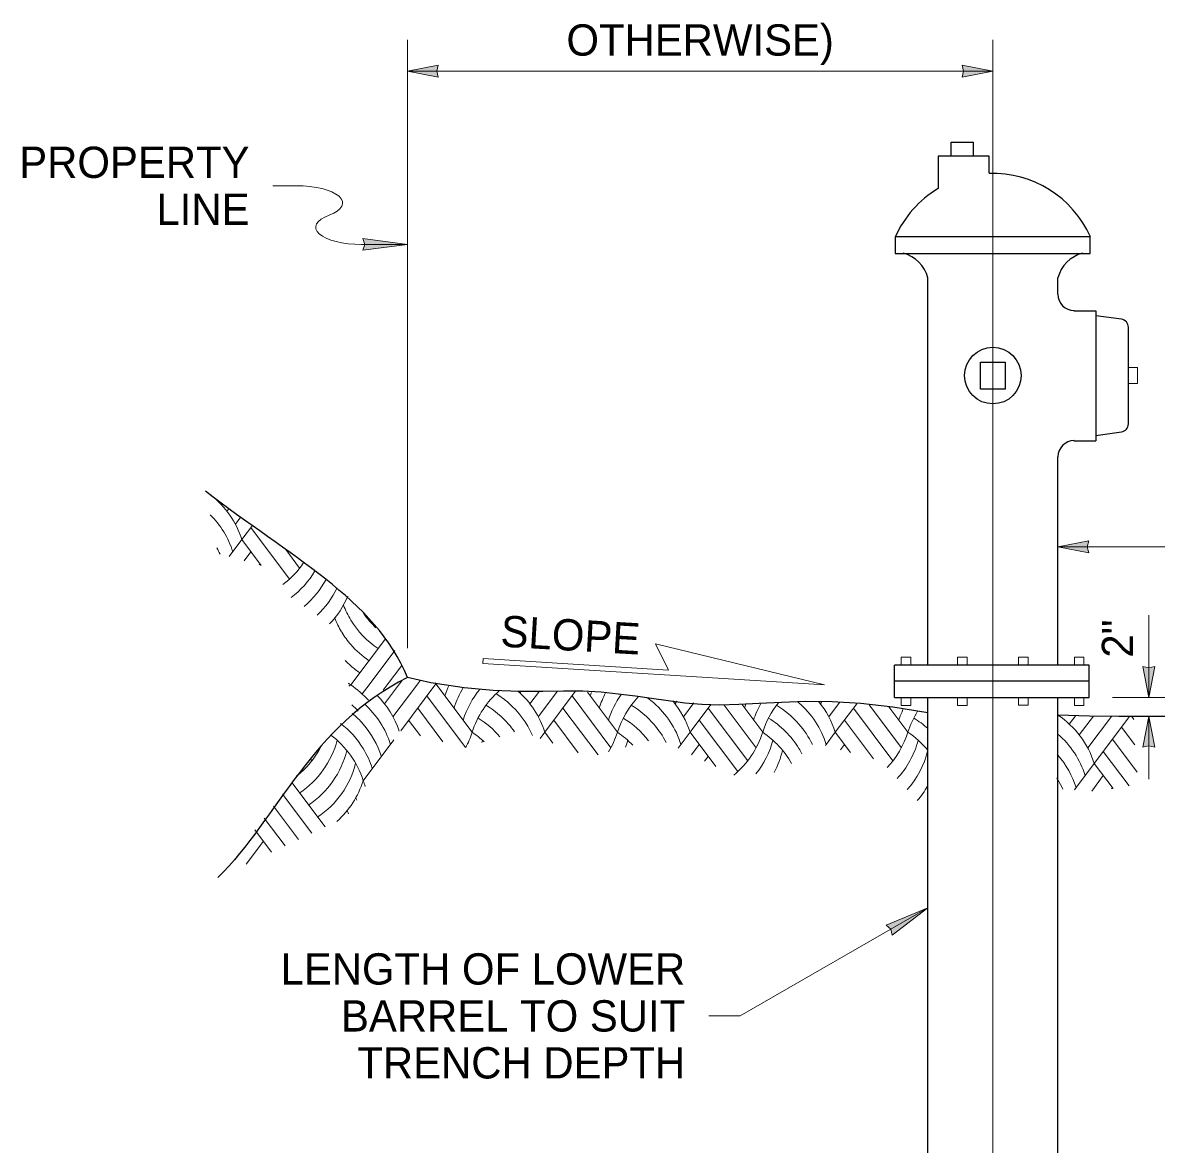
# Model space of a CAD drawing. Extents: x 99860 to 103153, y 99998 to 102077.
# Drawn here: x 101326 to 101906, y 100574 to 101147 of the extents above; entities that cross this region are included whole.
import ezdxf
from ezdxf.enums import TextEntityAlignment as Align

# ---------------------------------------------------------------- set-up
doc = ezdxf.new("R2010")
doc.units = 0
doc.header["$LTSCALE"] = 6.4
for name, color, linetype, lineweight in [('14', 7, 'Continuous', 13), ('15', 7, 'Continuous', 13), ('18', 7, 'Continuous', 13), ('2', 7, 'Continuous', 13), ('20', 7, 'Continuous', 13), ('3', 7, 'Continuous', 13), ('6', 7, 'Continuous', 25), ('8', 7, 'Continuous', 25)]:
    doc.layers.add(name, color=color, linetype=linetype, lineweight=lineweight)

msp = doc.modelspace()

# ---------------------------------------------------------------- hatches: boundary and pattern name
at = {"layer": '14'}
msp.add_hatch(color=256, dxfattribs=at).paths.add_polyline_path([(101523.114, 101033.874), (101500.285, 101030.889), (101501.341, 101033.874), (101500.284, 101036.859)])
at = {"layer": '15'}
for points in [[(101523.114, 101122.385), (101538.839, 101119.301), (101538.111, 101122.385), (101538.839, 101125.469)], [(101822.327, 101122.385), (101806.602, 101119.301), (101807.33, 101122.385), (101806.602, 101125.469)], [(101855.602, 100879.285), (101871.327, 100876.201), (101870.599, 100879.285), (101871.327, 100882.369)], [(101902.039, 100802.41), (101905.123, 100818.135), (101902.039, 100817.407), (101898.955, 100818.135)], [(101902.039, 100792.597), (101905.123, 100776.872), (101902.039, 100777.6), (101898.955, 100776.872)], [(101789.077, 100694.868), (101767.814, 100686.038), (101770.221, 100683.981), (101770.799, 100680.868)]]:
    msp.add_hatch(color=256, dxfattribs=at).paths.add_polyline_path(points)

# ---------------------------------------------------------------- linework, layer by layer
at = {"layer": '14'}
for p, q in [((101466.379, 101063.874), (101454.379, 101063.874)), ((101523.114, 101033.874), (101499.683, 101033.874))]:
    msp.add_line(p, q, dxfattribs=at)
msp.add_lwpolyline([(101523.114, 101033.874), (101500.285, 101030.889), (101501.341, 101033.874), (101500.284, 101036.859)], close=True, dxfattribs=at)
for centre, start_param, end_param in [((101466.547, 101055.087), 5.4977468, 7.8611267), ((101499.683, 101042.661), 2.3562263, 4.712389)]:
    msp.add_ellipse(centre, major_axis=(23.431, 0), ratio=0.375, start_param=start_param, end_param=end_param, dxfattribs=at)
at = {"layer": '15'}
for p, q in [((101523.114, 100827.522), (101523.114, 101138.385)), ((101822.327, 101138.385), (101822.327, 100280.712)), ((101523.114, 101122.385), (101822.327, 101122.385)), ((102119.127, 100879.285), (101855.602, 100879.285)), ((101902.039, 100802.41), (101902.039, 100844.393)), ((101883.539, 100802.41), (101918.039, 100802.41)), ((101902.039, 100760.597), (101902.039, 100792.597)), ((101789.077, 100694.868), (101693.093, 100639.597)), ((101677.093, 100639.597), (101693.093, 100639.597))]:
    msp.add_line(p, q, dxfattribs=at)
for points in [[(101523.114, 101122.385), (101538.839, 101119.301), (101538.111, 101122.385), (101538.839, 101125.469)], [(101822.327, 101122.385), (101806.602, 101119.301), (101807.33, 101122.385), (101806.602, 101125.469)], [(101855.602, 100879.285), (101871.327, 100876.201), (101870.599, 100879.285), (101871.327, 100882.369)], [(101902.039, 100802.41), (101905.123, 100818.135), (101902.039, 100817.407), (101898.955, 100818.135)], [(101902.039, 100792.597), (101905.123, 100776.872), (101902.039, 100777.6), (101898.955, 100776.872)], [(101789.077, 100694.868), (101767.814, 100686.038), (101770.221, 100683.981), (101770.799, 100680.868)]]:
    msp.add_lwpolyline(points, close=True, dxfattribs=at)
at = {"layer": '18', "lineweight": 25}
for p, q in [((101789.077, 100818.897), (101789.077, 101016.785)), ((101855.602, 101008.547), (101855.602, 101016.785)), ((101863.802, 101000.035), (101875.027, 101000.035)), ((101875.027, 101000.035), (101875.027, 100933.522)), ((101875.027, 100997.635), (101888.039, 100995.785)), ((101891.489, 100991.522), (101891.489, 100942.31)), ((101875.027, 100936.21), (101888.039, 100938.06)), ((101863.802, 100933.522), (101875.027, 100933.522)), ((101855.602, 100818.897), (101855.602, 100925.285)), ((101871.539, 100818.897), (101772.064, 100818.897)), ((101772.064, 100802.41), (101772.064, 100818.897)), ((101871.539, 100802.41), (101871.539, 100818.897)), ((101871.539, 100810.672), (101772.064, 100810.672)), ((101772.064, 100802.41), (101871.539, 100802.41))]:
    msp.add_line(p, q, dxfattribs=at)
at = {"layer": '18'}
for p, q in [((101896.302, 100971.047), (101891.489, 100971.047)), ((101896.302, 100971.047), (101896.302, 100962.81)), ((101896.302, 100962.81), (101891.489, 100962.81)), ((101775.427, 100822.972), (101780.389, 100822.972)), ((101775.427, 100818.897), (101775.427, 100822.972)), ((101780.389, 100822.972), (101780.389, 100818.897)), ((101804.227, 100822.947), (101809.189, 100822.947)), ((101804.227, 100818.897), (101804.227, 100822.947)), ((101809.189, 100822.947), (101809.189, 100818.897)), ((101835.402, 100822.972), (101840.364, 100822.972)), ((101835.402, 100818.897), (101835.402, 100822.972)), ((101840.364, 100818.897), (101840.364, 100822.972)), ((101863.989, 100822.91), (101868.914, 100822.91)), ((101863.989, 100818.897), (101863.989, 100822.91)), ((101868.914, 100822.91), (101868.914, 100818.897)), ((101775.427, 100798.31), (101775.427, 100802.41)), ((101780.389, 100802.41), (101780.389, 100798.31)), ((101804.227, 100798.31), (101804.227, 100802.41)), ((101809.189, 100802.41), (101809.189, 100798.31)), ((101835.402, 100798.335), (101835.402, 100802.41)), ((101840.364, 100798.335), (101840.364, 100802.41)), ((101863.989, 100798.272), (101863.989, 100802.41)), ((101868.914, 100802.41), (101868.914, 100798.272)), ((101775.427, 100798.31), (101780.389, 100798.31)), ((101804.227, 100798.31), (101809.189, 100798.31)), ((101835.402, 100798.335), (101840.364, 100798.335)), ((101863.989, 100798.272), (101868.914, 100798.272))]:
    msp.add_line(p, q, dxfattribs=at)
at = {"layer": '18', "lineweight": 25}
for points in [[(101801.052, 101079.01), (101801.052, 101086.222), (101812.239, 101086.222), (101812.239, 101079.01)], [(101820.477, 101070.247), (101820.477, 101079.01), (101794.414, 101079.01), (101794.414, 101062.535)]]:
    msp.add_lwpolyline(points, dxfattribs=at)
for points in [[(101872.064, 101029.272), (101872.064, 101037.772), (101772.339, 101037.772), (101772.339, 101029.272)], [(101815.939, 100959.86), (101815.939, 100973.697), (101828.702, 100973.697), (101828.702, 100959.86)]]:
    msp.add_lwpolyline(points, close=True, dxfattribs=at)
msp.add_circle((101822.336, 100966.861), 14.468, dxfattribs=at)
for centre, radius, start, end in [((101822.336, 101015.63), 54.543, 23.89556, 91.97586), ((101822.336, 101015.63), 54.543, 120.92859, 156.10444), ((101772.154, 101012.497), 17.465, 14.112, 75.60063), ((101872.519, 101012.497), 17.465, 104.39937, 165.888), ((101863.893, 101008.418), 8.311, 180, 270), ((101887.433, 100991.539), 4.156, 0, 81.50484), ((101887.433, 100942.184), 4.156, 278.49516, 0), ((101863.893, 100925.304), 8.311, 90, 180)]:
    msp.add_arc(centre, radius, start, end, dxfattribs=at)
at = {"layer": '2'}
for p, q in [((101425.756, 100903.13), (101425.94, 100903.374)), ((101430.853, 100897.551), (101431.941, 100899.001)), ((101435.157, 100890.915), (101437.942, 100894.628)), ((101438.5, 100882.998), (101443.943, 100890.255)), ((101443.141, 100889.186), (101462.88, 100862.867)), ((101431.998, 100874.328), (101438.5, 100882.998)), ((101438.5, 100882.998), (101448.347, 100869.869)), ((101439.702, 100872.227), (101443.141, 100876.811)), ((101460.871, 100877.92), (101467.976, 100868.446)), ((101447.407, 100870.126), (101447.781, 100870.624)), ((101501.831, 100843.697), (101501.935, 100843.836)), ((101506.928, 100838.118), (101506.937, 100838.131)), ((101494.184, 100808.752), (101511.913, 100832.392)), ((101503.465, 100808.752), (101516.651, 100826.334)), ((101512.745, 100808.752), (101520.217, 100818.714)), ((101500.001, 100804.135), (101503.465, 100808.752)), ((101510.715, 100806.045), (101512.745, 100808.752)), ((101511.423, 100799.121), (101519.07, 100809.317)), ((101515.727, 100792.485), (101528.351, 100809.317)), ((101519.07, 100809.317), (101520.245, 100810.884)), ((101519.65, 100785.342), (101537.632, 100809.317)), ((101528.351, 100809.317), (101529.685, 100811.096)), ((101537.286, 100809.778), (101537.632, 100809.317)), ((101537.632, 100809.317), (101556.193, 100784.568)), ((101532.991, 100803.13), (101552.796, 100776.723)), ((101580.571, 100804.7), (101581.254, 100805.61)), ((101585.668, 100799.121), (101590.535, 100805.61)), ((101589.972, 100792.485), (101599.815, 100805.61)), ((101593.315, 100784.568), (101608.894, 100805.34)), ((101607.236, 100803.13), (101627.095, 100776.651)), ((101615.069, 100805.061), (101630.438, 100784.568)), ((101659.913, 100799.121), (101660.881, 100800.412)), ((101528.351, 100796.943), (101541.267, 100779.721)), ((101602.596, 100796.943), (101620.516, 100773.049)), ((101664.217, 100792.485), (101669.561, 100799.611)), ((101667.56, 100784.568), (101678.241, 100798.809)), ((101676.841, 100796.943), (101697.036, 100770.016)), ((101684.961, 100798.491), (101701.34, 100776.651)), ((101693.962, 100798.864), (101704.683, 100784.568)), ((101734.158, 100799.121), (101734.833, 100800.02)), ((101738.462, 100792.485), (101743.906, 100799.743)), ((101741.805, 100784.568), (101752.726, 100799.129)), ((101751.086, 100796.943), (101771.281, 100770.016)), ((101759.193, 100798.507), (101775.585, 100776.651)), ((101769.195, 100797.546), (101778.928, 100784.568)), ((101523.711, 100790.756), (101529.739, 100782.719)), ((101597.956, 100790.756), (101610.452, 100774.094)), ((101672.201, 100790.756), (101691.94, 100764.437)), ((101746.446, 100790.756), (101761.325, 100770.916)), ((101861.419, 100788.755), (101864.667, 100793.086)), ((101866.516, 100783.176), (101873.778, 100792.859)), ((101870.82, 100776.54), (101882.932, 100792.69)), ((101874.163, 100768.623), (101892.152, 100792.609)), ((101893.304, 100792.599), (101894.422, 100791.109)), ((101590.973, 100781.445), (101593.315, 100784.568)), ((101593.315, 100784.568), (101597.507, 100778.979)), ((101661.404, 100776.36), (101667.56, 100784.568)), ((101667.56, 100784.568), (101680.705, 100767.042)), ((101736.731, 100777.803), (101741.805, 100784.568)), ((101741.805, 100784.568), (101749.578, 100774.206)), ((101888.084, 100787.185), (101894.854, 100778.158)), ((101500.509, 100759.82), (101516.151, 100780.676)), ((101668.218, 100773.07), (101672.201, 100778.381)), ((101744.401, 100775.655), (101746.446, 100778.381)), ((101883.444, 100780.998), (101896.036, 100764.208)), ((101478.536, 100776.743), (101478.605, 100776.651)), ((101675.031, 100769.781), (101676.841, 100772.194)), ((101878.803, 100774.811), (101892.029, 100757.177)), ((101473.625, 100770.918), (101474.301, 100770.016)), ((101864.044, 100755.132), (101874.163, 100768.623)), ((101874.163, 100768.623), (101883.752, 100755.838)), ((101468.756, 100765.035), (101469.205, 100764.437)), ((101872.868, 100754.523), (101878.803, 100762.436)), ((101464.035, 100758.955), (101481.102, 100736.2)), ((101883.05, 100755.724), (101883.444, 100756.249)), ((101459.314, 100752.876), (101474.247, 100732.965)), ((101454.592, 100746.797), (101467.392, 100729.731)), ((101449.871, 100740.718), (101460.537, 100726.496)), ((101445.15, 100734.639), (101453.683, 100723.261)), ((101440.628, 100717.101), (101449.466, 100728.884))]:
    msp.add_line(p, q, dxfattribs=at)
for centre, start, end in [((101393.738, 100868.762), 56.09536, 56.09634), ((101393.738, 100868.762), 56.08424, 56.09535), ((101393.738, 100868.762), 17.6434, 51.75329), ((101389.098, 100862.575), 17.6434, 44.93637), ((101384.457, 100856.387), 24.14971, 28.43402), ((101430.861, 100897.235), 307.55806, 326.43655), ((101435.502, 100891.048), 306.83176, 329.20914), ((101440.142, 100884.861), 310.01548, 331.83917), ((101444.782, 100878.674), 313.15031, 334.43121), ((101449.423, 100872.486), 316.24748, 337.04822), ((101534.307, 100866.299), 200.87781, 211.33197), ((101529.666, 100860.112), 201.43438, 211.11957), ((101534.306, 100866.299), 211.33188, 236.09639), ((101538.946, 100872.486), 215.27667, 227.20355), ((101529.666, 100860.112), 211.36516, 220.94161), ((101529.665, 100860.112), 220.94154, 236.09639), ((101525.026, 100853.925), 224.12628, 228.95992), ((101525.025, 100853.925), 228.95986, 236.09639), ((101520.386, 100847.738), 234.15274, 236.09639), ((101520.386, 100769.767), 123.90361, 125.44007), ((101467.983, 100769.767), 41.51201, 56.09634), ((101582.394, 100795.08), 161.86969, 162.3566), ((101587.035, 100788.893), 155.26186, 162.3566), ((101591.675, 100782.706), 148.44353, 162.3566), ((101596.315, 100776.519), 140.1689, 162.3566), ((101474.308, 100770.332), 18.35813, 45.07934), ((101600.956, 100770.332), 130.84642, 162.3566), ((101543.914, 100764.145), 48.95968, 58.54646), ((101548.553, 100770.332), 17.6434, 48.68118), ((101661.28, 100788.893), 159.98822, 162.3566), ((101665.92, 100782.706), 152.16202, 162.3566), ((101670.56, 100776.519), 144.51205, 162.3566), ((101675.201, 100770.332), 136.52962, 162.3566), ((101618.159, 100764.145), 48.95968, 53.7444), ((101622.798, 100770.332), 17.6434, 40.1409), ((101463.343, 100763.58), 42.5792, 48.06228), ((101469.668, 100764.145), 17.6434, 47.9305), ((101539.273, 100757.957), 40.94134, 59.30215), ((101543.913, 100764.145), 23.61782, 48.95974), ((101613.518, 100757.957), 40.94134, 59.30215), ((101618.158, 100764.145), 17.6434, 48.95974), ((101740.165, 100782.706), 159.76574, 162.3566), ((101744.805, 100776.519), 151.03088, 162.3566), ((101749.446, 100770.332), 141.35369, 162.3566), ((101687.763, 100757.957), 40.94134, 59.30215), ((101692.404, 100764.145), 48.95968, 49.94707), ((101692.403, 100764.145), 17.6434, 48.95974), ((101697.043, 100770.332), 17.6434, 39.27011), ((101814.41, 100782.706), 161.6604, 162.3566), ((101819.05, 100776.519), 154.83962, 162.3566), ((101823.691, 100770.332), 147.90308, 162.3566), ((101460.388, 100751.77), 31.33163, 52.57708), ((101465.028, 100757.957), 40.94134, 50.45234), ((101534.633, 100751.77), 40.47662, 58.48736), ((101608.878, 100751.77), 37.14403, 58.48736), ((101683.123, 100751.77), 31.33163, 58.48736), ((101757.368, 100751.77), 47.58354, 58.48736), ((101881.803, 100754.387), 123.90361, 123.90451), ((101829.401, 100754.387), 56.09551, 56.09634), ((101829.401, 100754.387), 17.6434, 56.09551), ((101455.748, 100745.583), 17.6434, 53.11513), ((101465.027, 100757.957), 17.6434, 40.94141), ((101511.431, 100798.805), 331.92959, 342.3566), ((101529.993, 100745.583), 46.49224, 56.09639), ((101539.272, 100757.957), 34.71219, 40.94141), ((101585.676, 100798.805), 328.87171, 342.3566), ((101604.238, 100745.583), 43.52341, 56.09639), ((101613.517, 100757.957), 26.9833, 40.94141), ((101659.921, 100798.805), 309.61014, 342.3566), ((101678.483, 100745.583), 29.36292, 56.09639), ((101687.762, 100757.957), 25.76242, 40.94141), ((101734.166, 100798.805), 316.50259, 342.3566), ((101752.728, 100745.583), 39.4164, 56.09639), ((101824.761, 100748.2), 48.95968, 49.27025), ((101824.76, 100748.2), 17.6434, 48.95974), ((101441.827, 100792.618), 303.90361, 345.01126), ((101516.072, 100792.618), 343.46672, 345.01126), ((101590.317, 100792.618), 340.46444, 345.01126), ((101664.562, 100792.618), 321.35054, 345.01126), ((101738.807, 100792.618), 317.45488, 345.01126), ((101437.186, 100798.805), 308.53107, 332.49969), ((101446.467, 100786.431), 303.90361, 346.31988), ((101460.387, 100751.77), 17.6434, 31.33172), ((101669.202, 100786.431), 331.54858, 346.31988), ((101683.122, 100751.77), 27.56971, 31.33172), ((101743.447, 100786.431), 318.40849, 345.95566), ((101820.121, 100742.012), 40.94134, 41.68711), ((101820.12, 100742.012), 17.6434, 40.94141), ((101451.107, 100780.244), 303.90361, 345.77133), ((101673.842, 100780.244), 345.56367, 345.77133), ((101455.748, 100774.056), 311.68299, 342.3566), ((101545.271, 100774.056), 197.64354, 201.39049), ((101815.481, 100735.825), 31.33163, 32.80985), ((101815.479, 100735.825), 24.81791, 31.33172), ((101748.087, 100780.244), 319.36371, 330.46941), ((101540.632, 100767.869), 200.87781, 202.46481), ((101535.991, 100761.682), 201.43438, 203.52627), ((101752.728, 100774.056), 320.32081, 320.39122), ((101531.351, 100755.495), 200.24322, 200.38305)]:
    msp.add_arc(centre, 46.972, start, end, dxfattribs=at)
at = {"layer": '3'}
msp.add_lwpolyline([(101561.77, 100822.196), (101656.564, 100816.279), (101649.907, 100829.679), (101736.275, 100808.825), (101561.616, 100819.726)], close=True, dxfattribs=at)
at = {"layer": '6'}
for p, q in [((101789.077, 100511.985), (101789.077, 100802.41)), ((101855.602, 100511.985), (101855.602, 100802.41))]:
    msp.add_line(p, q, dxfattribs=at)
at = {"layer": '8'}
for points in [[(101789.077, 100794.447), (101771.264, 100797.347), (101754.789, 100799.235), (101740.139, 100800.035), (101726.577, 100800.272), (101714.364, 100799.747), (101702.927, 100799.235), (101692.539, 100798.71), (101682.702, 100798.397), (101673.664, 100798.71), (101664.877, 100799.472), (101656.364, 100800.56), (101647.852, 100801.885), (101639.614, 100802.96), (101630.827, 100804.01), (101622.077, 100805.085), (101612.727, 100805.61), (101602.927, 100805.61), (101592.289, 100805.36), (101580.327, 100805.36), (101567.002, 100805.86), (101552.102, 100807.21), (101535.089, 100809.872), (101523.114, 100812.522)], [(101951.064, 100794.422), (101924.727, 100792.847), (101913.039, 100792.597), (101900.277, 100792.597), (101886.714, 100792.597), (101871.814, 100792.847), (101855.602, 100793.372)]]:
    msp.add_lwpolyline(points, dxfattribs=at)
for points in [[(101523.114, 100812.522), (101507.177, 100852.422), (101461.977, 100874.997), (101419.939, 100907.747)], [(101523.114, 100812.522), (101474.002, 100788.072), (101457.252, 100741.385), (101426.264, 100710.322)]]:
    msp.add_open_spline(points, degree=3, dxfattribs=at)

# ---------------------------------------------------------------- texts
at = {"layer": '20'}
msp.add_text('OTHERWISE)', height=16, dxfattribs=at).set_placement((101672.724, 101130.385), align=Align.CENTER)
for s, p in [('PROPERTY', (101442.387, 101067.874)), ('LINE', (101442.388, 101043.874)), ('LENGTH OF LOWER', (101665.097, 100655.597)), ('BARREL TO SUIT', (101665.097, 100631.597)), ('TRENCH DEPTH', (101665.097, 100607.597))]:
    msp.add_text(s, height=16, dxfattribs=at).set_placement(p, align=Align.RIGHT)
msp.add_text('SLOPE', height=16, rotation=356.677, dxfattribs=at).set_placement((101606.003, 100826.306), align=Align.CENTER)
msp.add_text('2"', height=16, rotation=90, dxfattribs=at).set_placement((101894.039, 100822.7))

doc.saveas('drawing.dxf')
